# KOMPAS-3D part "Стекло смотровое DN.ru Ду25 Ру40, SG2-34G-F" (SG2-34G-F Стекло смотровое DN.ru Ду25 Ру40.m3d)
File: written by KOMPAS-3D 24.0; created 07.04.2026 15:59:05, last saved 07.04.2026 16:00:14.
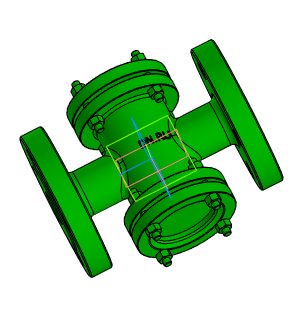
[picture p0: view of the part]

Document properties: Автор: Main; Полное имя файла: D:\DN.ru Аутсерс\Стекло смотровое DN.ru\SG2-34G-F Стекло смотровое DN.ru Ду25 Ру40\SG2-34G-F Стекло смотровое DN.ru Ду25 Ру40.m3d

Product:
- Body: Тело 1  | qty 1
    Масса: 4.394636
- Part/product: Стекло смотровое DN.ru Ду25 Ру40  | designation SG2-34G-F
    Масса: 5.5
    Раздел спецификации: Прочие изделия
    Примечание: D500-00081

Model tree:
1. Операция без истории:1

Expressions: SG2-34G-F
